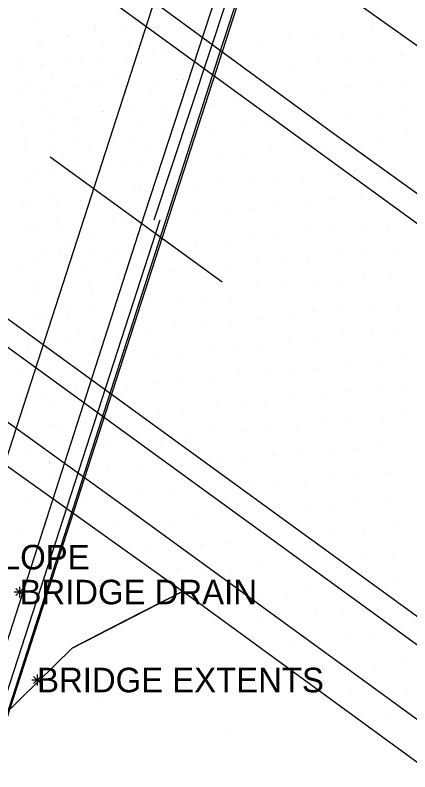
# Model space of a CAD drawing. Extents: x 0 to 1739264, y 0 to 465304.
# Drawn here: x 1738856.5 to 1738885.4, y 464637.2 to 464692.7 of the extents above; entities that cross this region are included whole.
import ezdxf

# ---------------------------------------------------------------- set-up
doc = ezdxf.new("R2010")
doc.units = 0
for name, color, linetype in [('Default', 7, 'Continuous'), ('S_Ground_SpotElevation', 7, 'Continuous'), ('S_Misc_MiscItems', 7, 'Continuous'), ('S_Terrain_Boundary', 7, 'Continuous'), ('S_Terrain_Flow_Arrows', 7, 'Continuous'), ('S_Terrain_Holes', 7, 'Continuous'), ('S_Terrain_Imported_Contours', 7, 'Continuous'), ('S_Terrain_Low_Points', 7, 'Continuous'), ('S_Terrain_Major_Contours_Label', 7, 'Continuous'), ('S_Terrain_Minor_Contours', 7, 'Continuous'), ('S_Terrain_Spots', 7, 'Continuous'), ('S_Terrain_Triangles', 7, 'Continuous'), ('S_Text', 7, 'Continuous')]:
    doc.layers.add(name, color=color, linetype=linetype)

# ---------------------------------------------------------------- blocks, each defined once
blk = doc.blocks.new('POINT_DISPLAY')
at = {"layer": 'Default'}
blk.add_line((0, 0), (0, 0), dxfattribs=at)

msp = doc.modelspace()

# ---------------------------------------------------------------- linework, layer by layer
at = {"layer": 'S_Misc_MiscItems'}
for p, q in [((1738857.094081, 464650.115919), (1738856.569919, 464650.640081)), ((1738857.094081, 464650.640081), (1738856.569919, 464650.115919)), ((1738856.832, 464650.770925), (1738856.832, 464649.985075)), ((1738857.224925, 464650.378), (1738856.439075, 464650.378)), ((1738858.514925, 464643.931), (1738857.729075, 464643.931)), ((1738858.384081, 464643.668919), (1738857.859919, 464644.193081)), ((1738858.384081, 464644.193081), (1738857.859919, 464643.668919)), ((1738858.122, 464644.323925), (1738858.122, 464643.538075))]:
    msp.add_line(p, q, dxfattribs=at)
at = {"layer": 'S_Terrain_Boundary'}
for points in [[(1739240.087209, 464422.512092), (1739204.20461, 464448.975806), (1739151.98821, 464486.847297), (1739077.545202, 464540.718299), (1739036.299199, 464570.587592), (1738998.913701, 464597.936805), (1738915.898401, 464658.026801), (1738879.6822, 464684.091499), (1738826.038202, 464723.403098), (1738785.838697, 464752.297202), (1738730.174596, 464792.732001), (1738678.937795, 464830.008598), (1738622.825002, 464870.7028), (1738578.496206, 464902.7599), (1738526.77361, 464940.2817), (1738487.876485, 464968.875201)], [(1738472.502187, 464946.8812), (1738532.782491, 464903.138), (1738592.890188, 464859.1697), (1738654.956395, 464814.352699), (1738729.403905, 464760.335593), (1738775.1778, 464727.296302), (1738818.718499, 464695.4598), (1738870.5623, 464657.690711), (1738915.532399, 464624.999397), (1738974.4306, 464582.450111), (1739023.977193, 464546.580512), (1739063.9643, 464517.371711), (1739099.458196, 464491.667609), (1739137.386403, 464464.308906), (1739199.037587, 464419.570075), (1739224.736989, 464400.957526)]]:
    msp.add_lwpolyline(points, dxfattribs=at)
at = {"layer": 'S_Terrain_Flow_Arrows'}
msp.add_lwpolyline([(1739139.267385, 464454.910011), (1739130.590291, 464461.71009), (1739110.595495, 464477.929694), (1739082.297796, 464498.495307), (1739049.266698, 464522.52439), (1739001.084997, 464557.32859), (1738948.1471, 464595.782996), (1738903.076001, 464628.553901), (1738864.8372, 464656.393409), (1738827.215101, 464683.576698), (1738805.826267, 464699.079322)], dxfattribs=at)
at = {"layer": 'S_Terrain_Holes'}
for points in [[(1738492.982015, 464976.242099), (1738514.851095, 464960.0815), (1738563.791494, 464924.7685), (1738624.996999, 464880.339801), (1738673.015905, 464845.222999), (1738705.323293, 464821.628898), (1738726.980504, 464805.7443), (1738753.122999, 464787.077293), (1738791.7562, 464758.973594), (1738812.206201, 464744.064307), (1738838.2751, 464724.973701), (1738870.6467, 464701.313407), (1738896.6608, 464682.840995), (1738936.578298, 464654.121894), (1738968.041097, 464631.189491), (1739001.793905, 464606.514411), (1739033.507696, 464583.63401), (1739053.896306, 464568.752204), (1739082.668798, 464547.766914), (1739122.612798, 464519.166297), (1739150.551503, 464498.742286), (1739185.599386, 464473.337501), (1739245.296285, 464429.765205)], [(1739223.494985, 464399.203315), (1739206.639089, 464411.075385), (1739195.55071, 464418.42237), (1739183.070699, 464424.168708), (1739164.312002, 464433.463508), (1739147.939412, 464441.200599), (1739136.380086, 464447.050605), (1739129.442586, 464453.881599), (1739122.632696, 464461.219215), (1739111.531896, 464473.605506), (1739085.152105, 464493.350288), (1739018.993001, 464541.064887), (1738930.6419, 464605.24491), (1738870.0376, 464649.515296), (1738848.5874, 464664.834815), (1738811.620401, 464691.772605), (1738795.161496, 464705.215995), (1738777.6461, 464720.745506), (1738753.229703, 464739.785499), (1738719.607595, 464763.978797), (1738664.632497, 464803.914802), (1738578.72289, 464866.369498), (1738525.878194, 464904.395299), (1738470.625997, 464944.2677)]]:
    msp.add_lwpolyline(points, dxfattribs=at)
at = {"layer": 'S_Terrain_Imported_Contours'}
msp.add_line((1738871.6593, 464673.088996), (1738859.0848, 464682.2378), dxfattribs=at)
for points in [[(1738486.786886, 464967.328601), (1738511.286214, 464949.6202), (1738544.3709, 464925.4377), (1738582.310689, 464897.903999), (1738620.877294, 464869.822101), (1738659.468999, 464841.841804), (1738694.403493, 464816.496497), (1738735.406698, 464786.775001), (1738771.038297, 464760.946204), (1738812.0253, 464731.080299), (1738852.9921, 464701.379905), (1738891.8019, 464673.129615), (1738927.017999, 464647.615485), (1738972.948697, 464614.396308), (1739021.394994, 464579.194892), (1739065.901006, 464546.893897), (1739094.060003, 464526.5232), (1739126.956991, 464502.811591), (1739168.727712, 464472.415687), (1739212.603414, 464440.554298), (1739239.28951, 464421.227393)], [(1738473.290487, 464948.323199), (1738505.971608, 464924.6372), (1738575.674489, 464873.970901), (1738632.579, 464832.433501), (1738679.622793, 464798.454398), (1738729.982305, 464762.007606), (1738794.297201, 464715.280997), (1738887.4227, 464647.539405), (1738945.963498, 464605.092414), (1739005.654607, 464561.761695), (1739053.679494, 464527.002113), (1739103.605703, 464490.864906), (1739143.362111, 464462.167487), (1739175.577993, 464438.694404), (1739209.519491, 464413.997199), (1739225.432607, 464402.38819)], [(1738816.833754, 464540.526168), (1738828.844899, 464576.996803), (1738841.383399, 464615.664314), (1738851.1298, 464645.487891), (1738867.0642, 464694.79), (1738880.224773, 464736.284008)]]:
    msp.add_lwpolyline(points, dxfattribs=at)
at = {"layer": 'S_Terrain_Low_Points'}
for points in [[(1738882.8352, 464729.589896), (1738865.96384, 464677.988066), (1738852.7233, 464636.911414), (1738851.7415, 464633.401588)], [(1738868.768823, 464650.421444), (1738864.5389, 464648.277198), (1738860.6901, 464646.271796), (1738855.580477, 464641.268905), (1738853.442893, 464638.131514), (1738850.651702, 464638.781989)]]:
    msp.add_lwpolyline(points, dxfattribs=at)
at = {"layer": 'S_Terrain_Major_Contours_Label'}
msp.add_lwpolyline([(1738885.395159, 464732.452095), (1738884.2943, 464729.028999), (1738875.3401, 464701.327995), (1738857.6966, 464646.653999), (1738844.752799, 464606.659614), (1738829.9694, 464560.926002), (1738822.141572, 464536.77828)], dxfattribs=at)
at = {"layer": 'S_Terrain_Minor_Contours'}
msp.add_line((1738866.688, 464677.65191), (1738883.905735, 464729.730556), dxfattribs=at)
msp.add_lwpolyline([(1738844.286302, 464607.201361), (1738848.147801, 464619.041197), (1738858.648407, 464651.422155), (1738867.135194, 464677.65191)], dxfattribs=at)
at = {"layer": 'S_Terrain_Spots'}
msp.add_lwpolyline([(1738850.651702, 464638.781989), (1738853.442893, 464638.131514), (1738855.580477, 464641.268905), (1738860.6901, 464646.271796), (1738868.768823, 464650.421444)], dxfattribs=at)
at = {"layer": 'S_Terrain_Triangles'}
msp.add_lwpolyline([(1738885.339743, 464732.493165), (1738884.4636, 464729.823402), (1738878.6737, 464712.005698), (1738871.4064, 464689.647605), (1738862.8085, 464662.946113), (1738850.8758, 464625.801398), (1738841.409499, 464596.833595), (1738830.533101, 464562.882606), (1738822.877599, 464539.516792), (1738822.019587, 464536.864414)], dxfattribs=at)

# ---------------------------------------------------------------- block references
at = {"layer": 'S_Ground_SpotElevation'}
for p in [(1738857.832393, 464692.151176), (1738868.600093, 464692.455315), (1738870.42799, 464692.208904), (1738872.451793, 464692.4082), (1738862.380108, 464691.575909), (1738862.389293, 464691.930168), (1738864.345806, 464691.6441), (1738866.520488, 464691.827008), (1738866.725001, 464691.7481), (1738860.319195, 464691.18301), (1738860.471797, 464691.141472), (1738878.576092, 464691.133206), (1738880.539287, 464691.380108), (1738882.607311, 464691.494106), (1738858.28709, 464690.802212), (1738864.833507, 464690.822868), (1738869.2532, 464690.704216), (1738874.690807, 464690.546612), (1738876.620189, 464690.837307), (1738858.393504, 464690.263908), (1738862.941997, 464690.303703), (1738868.516704, 464689.945202), (1738856.708797, 464689.420463), (1738860.526592, 464689.373501), (1738864.722698, 464689.648205), (1738866.663006, 464689.714108), (1738867.574, 464689.783073), (1738880.704387, 464689.364208), (1738882.776012, 464689.437405), (1738884.742901, 464689.737011), (1738858.390301, 464688.951), (1738861.293697, 464689.251396), (1738862.616192, 464689.231091), (1738865.775798, 464689.140068), (1738876.786693, 464688.816906), (1738878.804394, 464689.09251), (1738856.714489, 464688.738995), (1738859.239696, 464688.444572), (1738863.924007, 464688.319206), (1738870.812694, 464688.241986), (1738857.489894, 464687.688896), (1738866.643596, 464687.78999), (1738868.331401, 464687.925896), (1738868.852489, 464687.967297), (1738860.869091, 464687.361798), (1738862.087794, 464687.40551), (1738862.804912, 464687.423901), (1738864.833996, 464687.522289), (1738866.520106, 464687.275566), (1738880.95869, 464687.35249), (1738883.031109, 464687.43269), (1738884.879711, 464687.678204), (1738856.914898, 464686.928509), (1738858.552501, 464686.852001), (1738879.058391, 464687.06419), (1738860.187404, 464686.543571), (1738864.764796, 464686.372307), (1738869.000194, 464686.127209), (1738870.806804, 464686.114605), (1738872.815288, 464686.481304), (1738858.507594, 464685.929619), (1738862.917003, 464685.593071), (1738862.992687, 464685.598889), (1738865.092205, 464685.721691), (1738867.125286, 464685.827008), (1738885.192302, 464685.69801), (1738859.036785, 464685.17149), (1738861.050304, 464684.989208), (1738867.360393, 464685.316399), (1738881.097912, 464685.284405), (1738883.156597, 464685.358807), (1738857.142986, 464684.852185), (1738861.154002, 464684.890678), (1738865.598796, 464684.617485), (1738873.175792, 464684.469189), (1738875.102489, 464684.796704), (1738859.235896, 464683.978081), (1738867.243694, 464683.961498), (1738869.323894, 464683.984387), (1738871.184704, 464684.108593), (1738885.207714, 464683.827893), (1738861.111797, 464683.373303), (1738863.293285, 464683.542187), (1738863.617793, 464683.756889), (1738865.131115, 464683.551495), (1738867.972697, 464683.778618), (1738883.280498, 464683.599499), (1738857.2485, 464683.219169), (1738859.19331, 464683.057385), (1738861.862605, 464683.056694), (1738866.328197, 464682.791679), (1738877.469311, 464682.871594), (1738879.115307, 464683.074505), (1738857.196514, 464682.662487), (1738871.333294, 464682.149395), (1738873.250896, 464682.326306), (1738875.188793, 464682.656994), (1738860.031093, 464682.109184), (1738863.337993, 464681.654309), (1738864.357494, 464681.857414), (1738865.41859, 464681.780194), (1738867.204509, 464681.767101), (1738869.174297, 464681.844708), (1738858.219203, 464681.33239), (1738859.132305, 464681.071789), (1738861.335308, 464681.293286), (1738862.758601, 464681.195366), (1738879.625988, 464681.123089), (1738881.462902, 464681.373211), (1738857.274608, 464680.747692), (1738867.093501, 464680.846916), (1738873.579693, 464680.575787), (1738875.640911, 464680.6815), (1738877.60371, 464680.753308), (1738860.768703, 464680.428398), (1738865.352901, 464680.088615), (1738867.56361, 464680.017712), (1738869.515514, 464679.918682), (1738871.408214, 464680.404492), (1738859.091701, 464679.546013), (1738865.66801, 464679.713391), (1738883.7794, 464679.492901), (1738859.621685, 464679.0789), (1738861.326793, 464679.068188), (1738863.462291, 464679.250988), (1738863.506908, 464679.358574), (1738877.682415, 464678.888989), (1738879.851696, 464679.122387), (1738881.802196, 464679.129406), (1738857.1506, 464678.677299), (1738857.567211, 464678.659497), (1738861.575603, 464678.46978), (1738866.059901, 464678.307487), (1738873.745495, 464678.462597), (1738875.642986, 464678.781994), (1738859.621196, 464677.899589), (1738867.864788, 464677.987988), (1738869.752392, 464678.019299), (1738871.901806, 464678.175488), (1738863.664013, 464677.4026), (1738864.306499, 464677.441887), (1738865.746197, 464677.564587), (1738881.893596, 464677.224285), (1738883.842205, 464677.319805), (1738857.725902, 464677.062512), (1738857.988902, 464676.955864), (1738859.89439, 464676.982708), (1738861.702892, 464677.022106), (1738862.209804, 464676.645988), (1738873.926311, 464676.651684), (1738875.798107, 464676.684399), (1738877.747814, 464676.861309), (1738879.769603, 464677.122601), (1738869.810802, 464676.1385), (1738860.631694, 464675.909599), (1738865.020793, 464675.582817), (1738868.071697, 464675.892712), (1738871.906688, 464676.000805), (1738858.684505, 464675.310722), (1738859.8419, 464675.015209), (1738861.968609, 464675.194317), (1738864.106792, 464675.378491), (1738865.930095, 464675.42329), (1738878.021007, 464674.973492), (1738880.206798, 464675.147717), (1738882.057689, 464675.169903), (1738884.111095, 464675.281414), (1738857.846996, 464674.893505), (1738863.237697, 464674.855827), (1738874.177898, 464674.59602), (1738876.144298, 464674.675213), (1738856.981593, 464674.239982), (1738861.467296, 464674.034904), (1738867.874187, 464673.85722), (1738869.933513, 464673.901196), (1738872.307995, 464674.297009), (1738864.124706, 464673.437512), (1738866.136394, 464673.579296), (1738882.044109, 464673.263195), (1738884.088695, 464673.650311), (1738858.058605, 464672.777813), (1738859.5937, 464673.233024), (1738860.105694, 464673.085308), (1738861.874706, 464673.202313), (1738863.941905, 464673.06237), (1738876.2765, 464672.82359), (1738878.31361, 464672.935803), (1738880.36961, 464673.078594), (1738857.770198, 464672.355278), (1738874.198711, 464672.702191), (1738862.098994, 464672.1278), (1738866.20219, 464671.669293), (1738868.326488, 464671.853314), (1738870.187694, 464671.901104), (1738872.25349, 464672.065197), (1738860.437907, 464671.411491), (1738862.259502, 464671.270916), (1738864.346996, 464671.332714), (1738880.440593, 464671.190319), (1738882.549511, 464671.327618), (1738884.643902, 464671.452404), (1738858.313915, 464670.673809), (1738858.498103, 464670.511101), (1738860.38911, 464670.83659), (1738876.605907, 464670.823406), (1738878.267498, 464671.018109), (1738863.100993, 464670.361687), (1738870.47279, 464670.094006), (1738872.330303, 464670.156903), (1738874.547405, 464670.387005), (1738856.680202, 464669.746879), (1738861.191096, 464669.517204), (1738866.456402, 464669.562695), (1738868.253002, 464669.861218), (1738884.484813, 464669.459606), (1738860.404491, 464668.905895), (1738862.427105, 464669.126507), (1738864.474712, 464669.22929), (1738880.530987, 464669.212902), (1738882.67979, 464669.184918), (1738858.46989, 464668.809918), (1738859.451701, 464668.814873), (1738874.649303, 464668.288616), (1738876.614513, 464668.603619), (1738878.542003, 464668.690197), (1738857.383495, 464668.041923), (1738862.051097, 464667.901726), (1738866.726085, 464667.748699), (1738868.539501, 464667.783703), (1738870.661999, 464668.243695), (1738872.75111, 464668.139599), (1738864.631115, 464667.357098), (1738880.933208, 464667.308605), (1738884.847606, 464667.707012), (1738860.126094, 464666.862602), (1738860.940105, 464667.072796), (1738862.556804, 464667.150402), (1738878.641796, 464666.775311), (1738882.968609, 464667.129101), (1738856.609203, 464666.507092), (1738858.427501, 464666.183586), (1738870.818493, 464666.100811), (1738872.844402, 464666.224407), (1738875.088787, 464666.467694), (1738876.804302, 464666.447705), (1738866.923198, 464665.630108), (1738868.782512, 464665.957195), (1738860.981593, 464665.069084), (1738862.7635, 464665.129894), (1738864.722088, 464665.412792), (1738880.967693, 464665.08952), (1738883.141399, 464665.113018), (1738885.116497, 464665.38139), (1738856.81831, 464664.624798), (1738858.868389, 464664.798901), (1738874.850689, 464664.40202), (1738876.992107, 464664.86079), (1738878.935711, 464664.68211), (1738859.014796, 464664.267692), (1738871.224895, 464663.919811), (1738873.076092, 464664.104595), (1738857.163402, 464663.446098), (1738865.015301, 464663.328106), (1738867.118603, 464663.495007), (1738868.874614, 464663.780194), (1738885.090099, 464663.455609), (1738861.274791, 464662.906811), (1738879.175304, 464662.847607), (1738881.111889, 464662.943707), (1738883.417186, 464663.208904), (1738857.091594, 464662.477703), (1738859.074291, 464662.668804), (1738859.928798, 464662.585808), (1738871.141796, 464662.194103), (1738873.127697, 464662.178204), (1738875.197796, 464662.333508), (1738877.084392, 464662.681103), (1738858.112697, 464661.736381), (1738869.372204, 464661.682507), (1738863.194195, 464661.093701), (1738867.151897, 464661.516796), (1738883.19099, 464661.421093), (1738857.282909, 464660.589001), (1738859.245189, 464660.743908), (1738860.559108, 464660.653923), (1738861.370708, 464661.003613), (1738877.359508, 464660.5872), (1738879.56541, 464660.802593), (1738881.551006, 464660.924206), (1738871.567608, 464660.048016), (1738873.402385, 464660.141094), (1738875.3419, 464660.461193), (1738858.998302, 464659.871391), (1738857.143596, 464659.186516), (1738861.640697, 464658.915997), (1738863.320995, 464659.190197), (1738865.444896, 464659.357098), (1738879.778698, 464658.959698), (1738881.613811, 464659.005108), (1738883.684612, 464659.163616), (1738859.401104, 464658.837414), (1738875.640301, 464658.378094), (1738877.796795, 464658.569317), (1738859.665507, 464657.937126), (1738865.626903, 464657.746319), (1738873.564403, 464658.223095), (1738857.647899, 464657.233208), (1738863.498394, 464657.213116), (1738867.879589, 464657.616314), (1738883.818615, 464657.28999), (1738861.528301, 464657.133099), (1738879.763988, 464656.740216), (1738881.602794, 464657.059796), (1738875.905315, 464656.564099), (1738877.773998, 464656.502606), (1738858.710796, 464655.533928), (1738869.698894, 464655.788403), (1738863.771312, 464655.395703), (1738865.89381, 464655.3195), (1738867.906109, 464655.501019), (1738882.034008, 464655.043591), (1738884.215404, 464655.253491), (1738856.934199, 464654.602226), (1738877.862591, 464654.725201), (1738879.897411, 464654.866619), (1738872.187908, 464653.945904), (1738866.290203, 464653.472119), (1738867.929302, 464653.766491), (1738870.112804, 464653.780712), (1738857.742, 464652.8377), (1738880.158397, 464653.043499), (1738882.024608, 464653.099499), (1738884.141613, 464653.260693), (1738874.204906, 464652.362011), (1738868.329296, 464652.007397), (1738870.209209, 464651.795819), (1738872.286205, 464652.075299), (1738882.498607, 464651.389904), (1738884.465404, 464651.203716), (1738862.703004, 464650.758892), (1738878.213207, 464650.699108), (1738872.497509, 464650.095013), (1738874.301891, 464650.182598), (1738876.491192, 464650.332714), (1738884.612713, 464649.213909), (1738876.478893, 464648.437298), (1738878.608288, 464648.6591), (1738880.586315, 464648.777203), (1738874.507213, 464648.245709), (1738876.648998, 464646.677807), (1738881.067913, 464647.082318), (1738882.776287, 464647.033917), (1738878.818493, 464646.570812), (1738882.872509, 464645.020001), (1738885.073498, 464645.287213), (1738879.165508, 464644.640209), (1738881.008404, 464644.766613), (1738881.113201, 464642.816601), (1738883.248699, 464642.985699), (1738885.250194, 464643.206616), (1738862.842103, 464642.419293), (1738883.618389, 464641.16499), (1738885.211101, 464641.34129), (1738872.130494, 464639.907391)]:
    msp.add_blockref('POINT_DISPLAY', p, dxfattribs=at)

# ---------------------------------------------------------------- texts
at = {"layer": 'S_Text'}
for s, p in [('PAVED SLOPE', (1738845.109, 464652.0359)), ('BRIDGE DRAIN', (1738856.832, 464649.478)), ('BRIDGE EXTENTS', (1738858.122, 464643.031))]:
    msp.add_text(s, height=1.8, dxfattribs=at).set_placement(p)

doc.saveas('drawing.dxf')
